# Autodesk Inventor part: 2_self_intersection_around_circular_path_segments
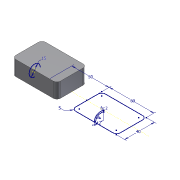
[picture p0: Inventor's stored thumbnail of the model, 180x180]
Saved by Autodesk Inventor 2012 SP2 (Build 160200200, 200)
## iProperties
Company: Autodesk, Inc.
Created: 2013-06
Part Number: 2_self_intersection_around_circular_path_segments
Material: Default
Document SubType Name: Modeling
Designer: Glenn Chun
Density: 1 g/cm^3
Author: Glenn Chun
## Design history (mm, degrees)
sketch "Sketch1"
  geometry: L1 (-30, 20)-(30, 20); L2 (30, 20)-(30, -20); L3 (30, -20)-(-30, -20); L4 (-30, -20)-(-30, 20); L5 (-30, 20)-(30, -20); 2 further points
  constraints: 10 end point, 2 parallel, 1 coincident, 1 horizontal, 1 midpoint, 1 perpendicular
  dimensions: "d0" = 60 distance of L2.end L3.end; "d1" = 40 distance of L1.end L2.end
extrude "Extrusion1" new body sketch "Sketch1" distance "d2" = 20; taper "d3" = 0 deg
fillet "Fillet1" dims "d4" = 5
sketch "Profile1 for sweep cut"
  geometry: C1 r 7.5 at (-20, 20); 1 further point
  constraints: 1 centre point, 1 coincident
  dimensions: "d5" = 15 diameter of C1
sketch "Path2"
  geometry: L1 (55, 20)-(105, 20); L2 (110, 15)-(110, -15); L3 (105, -20)-(55, -20); L4 (50, -15)-(50, 15); L5 (-22.207, 0)-(133.243, 0) reference; A1 r 5 centre (55, -15) between (50, -15) and (55, -20); A2 r 5 centre (105, -15) between (105, -20) and (110, -15); A3 r 5 centre (105, 15) between (110, 15) and (105, 20); A4 r 5 centre (55, 15) between (55, 20) and (50, 15); 5 further points
  constraints: 8 end point, 8 point on circle, 8 tangent, 7 point on line, 4 centre point, 3 equal radius, 2 parallel, 1 horizontal, 1 midpoint, 1 perpendicular
  dimensions: "d6" = 50 distance from line of point (0, 0) L4; "d7" = 60 distance of point (50, 20) point (110, 20); "d8" = 40 distance of point (110, 20) point (110, -20); "d9" = 5 radius of A1
node "Plane for Profile2"
sketch "Profile2"
  geometry: L1 (-18, 0)-(-20, 0); L2 (-12, 8)-(-8, 8); L3 (-8, 8)-(-8, 6); L4 (-8, 6)-(-12, 6); A1 r 8 centre (-12, 0) between (-12, 8) and (-20, 0); A2 r 6 centre (-12, 0) between (-12, 6) and (-18, 0)
  constraints: 8 end point, 4 point on circle, 2 centre point, 2 parallel, 1 concentric, 1 horizontal, 1 perpendicular, 1 tangent
  dimensions: "d11" = 2 distance of L1.start L1.end; "d12" = 2 distance of L2.end L3.end (= d11); "d13" = 12 distance from line of L3 L1.end; "d14" = 8 radius of A1; "d15" = 6 radius of A2
body "Solid1"
